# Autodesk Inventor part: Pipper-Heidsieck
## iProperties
Shininess: 64.0
Length Units: 11269
Angle Units: 11279
Time Units: 11290
Mass Units: 11283
Length Display Precision: 3
Angle Display Precision: 2
Compacted: True
Part Number: Pipper-Heidsieck
Document SubType Name: Modeling
Created: 2003-12
Material: Standard
Designer: Sec
Manufacturer: Standard
Standards Organization: Custom
Density: 0.0
Volumn: 0.0
Area: 0.0
PropertySet Name: Model Information
Control State: 0
Master: False
Checked Out: False
Author: Sec
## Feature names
1. Drehung1 [Revolution]
2. Rundung1 [Fillet]
3. Wandstärke1
4. Rundung2 [Fillet]
5. Trennen1
